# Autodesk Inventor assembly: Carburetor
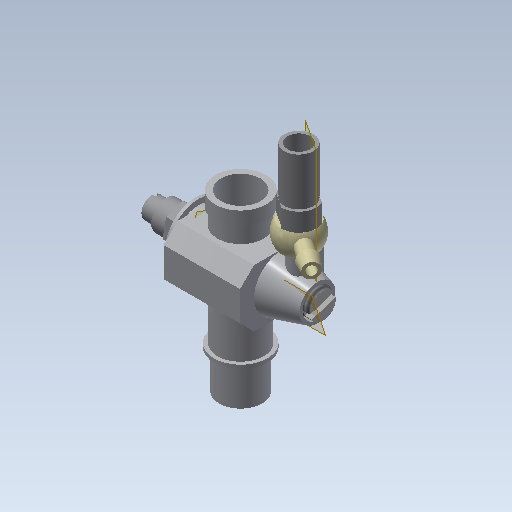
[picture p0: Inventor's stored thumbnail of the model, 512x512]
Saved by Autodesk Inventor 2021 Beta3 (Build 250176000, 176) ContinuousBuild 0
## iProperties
Created: 2012-08
Part Number: Carburetor
Document SubType Name: Assembly
Designer: John
Author: John
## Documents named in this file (8)
- C:\Users\John Helfen\Desktop\Ex_Files_Autodesk_Inventor_2020_EssT\Ex_Files_Autodesk_Inventor_2021_EssT\Exercise Files\03_Navigating the interface\03_02\Carburetor.iam
- C:\Users\John Helfen\Desktop\Ex_Files_Autodesk_Inventor_2020_EssT\Ex_Files_Autodesk_Inventor_2021_EssT\Exercise Files\03_Navigating the interface\03_02\Gas Regulator.ipt
- C:\Users\John Helfen\Desktop\Ex_Files_Autodesk_Inventor_2020_EssT\Ex_Files_Autodesk_Inventor_2021_EssT\Exercise Files\03_Navigating the interface\03_02\Mixture Control.ipt
- C:\Users\John Helfen\Desktop\Ex_Files_Autodesk_Inventor_2020_EssT\Ex_Files_Autodesk_Inventor_2021_EssT\Exercise Files\03_Navigating the interface\03_02\Air Adjuster.ipt
- C:\Users\John Helfen\Desktop\Ex_Files_Autodesk_Inventor_2020_EssT\Ex_Files_Autodesk_Inventor_2021_EssT\Exercise Files\03_Navigating the interface\03_02\Hex Cap.ipt
- C:\Users\John Helfen\Desktop\Ex_Files_Autodesk_Inventor_2020_EssT\Ex_Files_Autodesk_Inventor_2021_EssT\Exercise Files\03_Navigating the interface\03_02\Fuel Intake.ipt
- C:\Users\John Helfen\Desktop\Ex_Files_Autodesk_Inventor_2020_EssT\Ex_Files_Autodesk_Inventor_2021_EssT\Exercise Files\03_Navigating the interface\03_02\Fuel Adjuster.ipt
- C:\Users\John Helfen\Desktop\Ex_Files_Autodesk_Inventor_2020_EssT\Ex_Files_Autodesk_Inventor_2021_EssT\Exercise Files\03_Navigating the interface\03_02\Carburetor Housing_v3.ipt
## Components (7 placed, 7 different names)
1. Carburetor Housing_v3:2 — Mate:6, Mate:7, Mate:10, Flush:1, Flush:2
2. Gas Regulator:1 — Mate:6, Flush:1
3. Mixture Control:1 — Flush:2
4. Air Adjuster:1
5. Hex Cap:1
6. Fuel Intake:1 — Mate:8, Mate:9, Mate:10
7. Fuel Adjuster:1 — Mate:7, Mate:8, Mate:9
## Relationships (7: Mate 5, Flush 2)
- Mate:6: Carburetor Housing_v3:2 ↔ Gas Regulator:1
- Mate:7: Carburetor Housing_v3:2 ↔ Fuel Adjuster:1
- Mate:8: Fuel Intake:1 ↔ Fuel Adjuster:1
- Mate:9: Fuel Intake:1 ↔ Fuel Adjuster:1
- Mate:10: Carburetor Housing_v3:2 ↔ Fuel Intake:1
- Flush:1: Carburetor Housing_v3:2 ↔ Gas Regulator:1
- Flush:2: Carburetor Housing_v3:2 ↔ Mixture Control:1
